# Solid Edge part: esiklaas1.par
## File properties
Author: Mac
Template: Normal.par
Last saved by: Mac
Revision: 5
Application: Solid Edge
Material: Glass, general industrial
Face Style: White (glass)
Fill Style: ANSI36(Marble)
Virtual Style: White (Glass)
Coef. of Thermal Exp: 0.0
Thermal Conductivity: 0.0
Specific Heat: 0.0
Modulus of Elasticity: 0.0
Poission's Ratio: 0.0
Yield Stress: 0.0
Ultimate Stress: 0.0
Elongation: 0.0
Density: 2595,000 kg/m^3
Accuracy: 0,990
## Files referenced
..\Asm13.asm
=C:\Documents and Settings\Mac\Desktop\copy of paat2\Asm13.asm
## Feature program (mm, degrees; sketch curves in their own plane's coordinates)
sketch for "unnamed Protrusion 1" plane through (0, 0, 0) normal (1, 0, 0) x-axis (0, 1, 0)
  line (0, 13.4562) -> (0, 0)
  line (23.0058, 0) -> (0, 0)
  line (23.0058, 0) -> (23.0058, 13.4562)
  line (0, 13.4562) -> (23.0058, 13.4562)
extrude "unnamed Protrusion 1" add finite 28.4478 along -normal
replace surface "unnamed ReplaceSurface 1"
replace surface "unnamed ReplaceSurface 2"
body pattern "unnamed BodyPattern 1"
pattern "unnamed Pattern 1"
Other named dimensions: "OffsetSurface_1": Distance = 0.08 mm
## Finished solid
Body 1: sheet body, 1 face, 4 edges, 4 vertices.
  Faces by surface: offset 1
  Edges by curve: curve on surface 4
Body 2: solid body, 8 faces, 18 edges, 12 vertices.
  Faces by surface: plane 4, offset 2, spline 2
  Edges by curve: intersection 11, line 4, curve on surface 3
Body 3: sheet body, 1 face, 4 edges, 4 vertices.
  Faces by surface: spline 1
  Edges by curve: spline 4
Bounding box of the edges (mm; curved faces can reach further): 27.797 x 46.038 x 13.526, from (-27.667, -23.0058, 0) to (0.1301, 23.0324, 13.526).
Planar faces by outward normal: +y 1, +z 1, -y 1, -z 1
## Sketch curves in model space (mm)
spline (-20.3909, 0, 13.4562) -> (-22.637, 12.0063, 13.4562) -> (-27.667, 23.0058, 13.4562)
spline (-27.667, 23.0058, 13.4562) -> (-17.214, 23.0058, 7.1195) -> (-7.2776, 23.0058, 0)
spline (-7.2776, 23.0058, 0) -> (-2.2455, 12.0029, 0) -> (0, 0, 0)
spline (-20.3909, 0, 13.4562) -> (-9.9372, 0, 7.1195) -> (0, 0, 0)
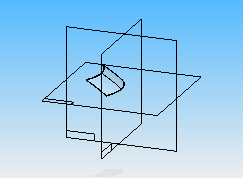
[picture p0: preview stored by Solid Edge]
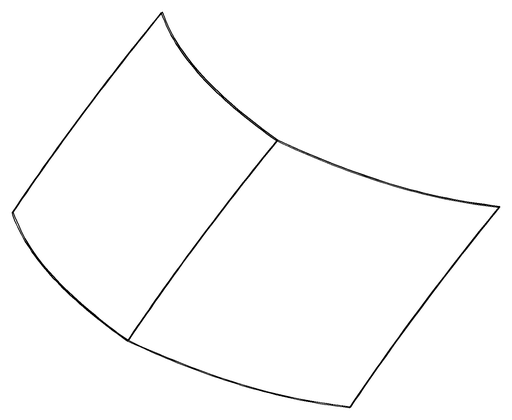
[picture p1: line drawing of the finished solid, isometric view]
